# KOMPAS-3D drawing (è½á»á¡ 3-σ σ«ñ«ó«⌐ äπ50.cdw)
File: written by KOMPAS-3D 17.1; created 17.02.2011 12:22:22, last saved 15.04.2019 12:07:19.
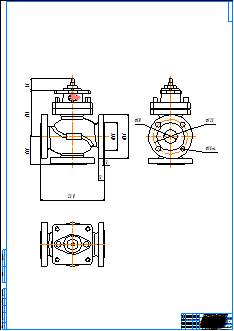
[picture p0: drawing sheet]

Title block, sheet 1: name: Клапан 3-х ходовой Ду50; material: Внимание! Данный продукт является объектом авторского права ООО «Торговый Дом АДЛ». / Запрещается изменение, копирование, распространение / (в том числе путем копирования на другие сайты и ресурсы в Интернете) / или любое иное использование информации и объектов без предварительного / согласия правообладателя (ООО «Торговый Дом АДЛ»).; scale: 1:1; sheets: 1; organisation: ООО "Торговый дом АДЛ"; sheet format: A0; stored path: \\adlc.lan\data\АДЛ_ПКД\3D-модели\ADL production\Клапаны ГРАНРЕГ\Трёхходовой клапан КМ307Ф\KOMPAS 2D\Клапан 3-х ходовой Ду50.cdw

Views: Спереди 1, Проекционный вид 2, Проекционный вид 3
Dimensions and other numbers on the sheet: 100; 166; 43; 230; 3; 23; 102; 160; 125; 18; 50; 1:1; 1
